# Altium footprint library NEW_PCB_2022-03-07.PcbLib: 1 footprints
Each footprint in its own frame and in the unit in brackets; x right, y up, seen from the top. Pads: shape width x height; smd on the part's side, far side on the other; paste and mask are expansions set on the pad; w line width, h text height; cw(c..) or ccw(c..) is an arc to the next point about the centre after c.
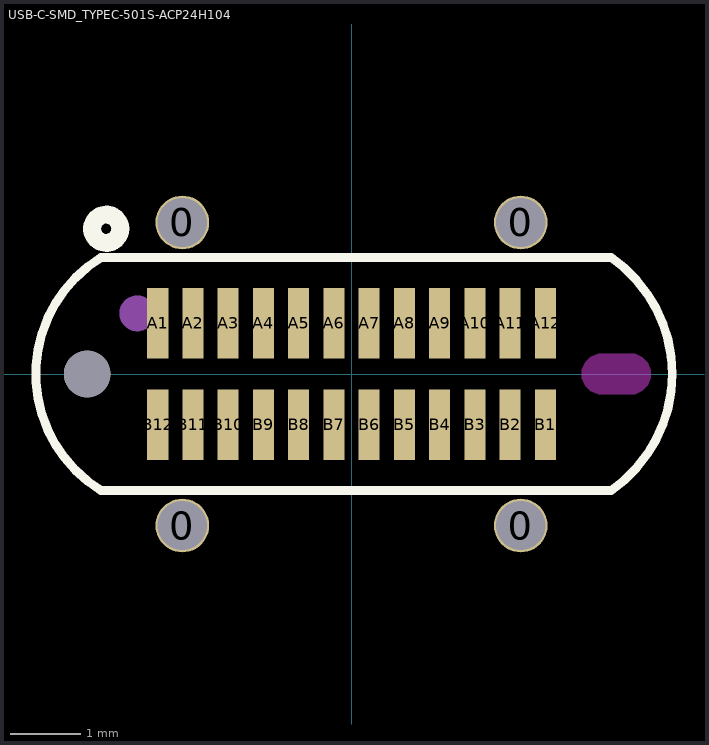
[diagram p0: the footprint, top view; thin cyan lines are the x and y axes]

## USB-C-SMD_TYPEC-501S-ACP24H104 [mm]
pads (29):
  round 0.762 hole 0.7: 0(-2.4,-2.15) 0(-2.4,2.15) 0(2.4,-2.15) 0(2.4,2.15)
  rect 0.3x1 smd: A1(-2.75,0.72) A2(-2.25,0.72) A3(-1.75,0.72) A4(-1.25,0.72) A5(-0.75,0.72) A6(-0.25,0.72) A7(0.25,0.72) A8(0.75,0.72) A9(1.25,0.72) A10(1.75,0.72) A11(2.25,0.72) A12(2.75,0.72) B1(2.75,-0.72) B2(2.25,-0.72) B3(1.75,-0.72) B4(1.25,-0.72) B5(0.75,-0.72) B6(0.25,-0.72) B7(-0.25,-0.72) B8(-0.75,-0.72) B9(-1.25,-0.72) B10(-1.75,-0.72) B11(-2.25,-0.72) B12(-2.75,-0.72)
  round 0.66 hole 0.66 unplated: ""(-3.75,0)
Top Overlay:
  circle w0.254: c-3.48,2.06 r0.2
  lines w0.125: -3.556,-1.651 cw(c-2.54,0) -3.556,1.651 3.683,1.651 cw(c2.54,0) 3.683,-1.651 -3.556,-1.651
Top Paste:
  circle w0.65: c-2.4,2.15 r0.325
  circle w0.65: c-2.4,-2.15 r0.325
  circle w0.65: c2.4,-2.15 r0.325
  circle w0.65: c2.4,2.15 r0.325
  region: -2.9,1.22 -2.6,1.22 -2.6,0.22 -2.9,0.22
  region: -0.4,1.22 -0.1,1.22 -0.1,0.22 -0.4,0.22
  region: -2.4,1.22 -2.1,1.22 -2.1,0.22 -2.4,0.22
  region: -1.9,1.22 -1.6,1.22 -1.6,0.22 -1.9,0.22
  region: -1.4,1.22 -1.1,1.22 -1.1,0.22 -1.4,0.22
  region: -0.9,1.22 -0.6,1.22 -0.6,0.22 -0.9,0.22
  region: 2.6,1.22 2.9,1.22 2.9,0.22 2.6,0.22
  region: 0.1,1.22 0.4,1.22 0.4,0.22 0.1,0.22
  region: 0.6,1.22 0.9,1.22 0.9,0.22 0.6,0.22
  region: 1.1,1.22 1.4,1.22 1.4,0.22 1.1,0.22
  region: 1.6,1.22 1.9,1.22 1.9,0.22 1.6,0.22
  region: 2.1,1.22 2.4,1.22 2.4,0.22 2.1,0.22
  region: -2.9,-0.22 -2.6,-0.22 -2.6,-1.22 -2.9,-1.22
  region: -0.4,-0.22 -0.1,-0.22 -0.1,-1.22 -0.4,-1.22
  region: -2.4,-0.22 -2.1,-0.22 -2.1,-1.22 -2.4,-1.22
  region: -1.9,-0.22 -1.6,-0.22 -1.6,-1.22 -1.9,-1.22
  region: -1.4,-0.22 -1.1,-0.22 -1.1,-1.22 -1.4,-1.22
  region: -0.9,-0.22 -0.6,-0.22 -0.6,-1.22 -0.9,-1.22
  region: 2.6,-0.22 2.9,-0.22 2.9,-1.22 2.6,-1.22
  region: 0.1,-0.22 0.4,-0.22 0.4,-1.22 0.1,-1.22
  region: 0.6,-0.22 0.9,-0.22 0.9,-1.22 0.6,-1.22
  region: 1.1,-0.22 1.4,-0.22 1.4,-1.22 1.1,-1.22
  region: 1.6,-0.22 1.9,-0.22 1.9,-1.22 1.6,-1.22
  region: 2.1,-0.22 2.4,-0.22 2.4,-1.22 2.1,-1.22
Keep-Out Layer:
  board cut-out: 3.97,-0.29 3.968,-0.29
  board cut-out: 4.244,0 4.244,-0.056 4.203,-0.16 4.126,-0.241 4.024,-0.287 3.968,-0.29 3.556,-0.29 3.499,-0.289 3.393,-0.245 3.312,-0.163 3.268,-0.057 3.268,0 3.268,0.058 3.312,0.164 3.393,0.245 3.499,0.29 3.556,0.29 3.97,0.29 4.026,0.287 4.127,0.24 4.203,0.159 4.244,0.056 4.244,0
Mechanical 15:
  circle w0.254: c-3.04,0.86 r0.127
